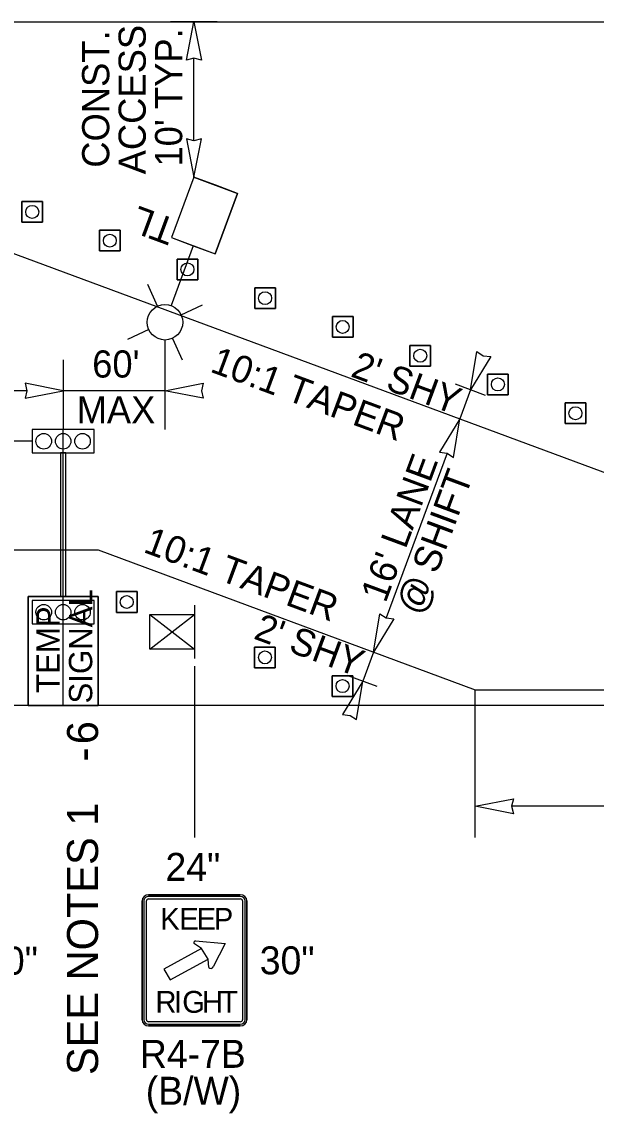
# Model space of a CAD drawing. Extents: x 99982 to 100176, y 99905 to 100011.
# Drawn here: x 100050.993 to 100052.474, y 99945.129 to 99947.939 of the extents above; entities that cross this region are included whole.
import ezdxf

# ---------------------------------------------------------------- set-up
doc = ezdxf.new("R2010")
doc.units = 0
for name, color, linetype in [('RD_ED_ShoulderPavedEdge', 7, 'Continuous'), ('RD_MK_LineEdgeWhite', 7, 'Continuous'), ('TR_SN_ConstructionSigns', 7, 'Continuous'), ('TR_WZ_PortableLightStandard', 7, 'Continuous'), ('TR_WZ_PortableSignMount5ftMinBlk-Wht', 7, 'Continuous'), ('TR_WZ_TempSignal', 7, 'Continuous'), ('TR_WZ_TrafficCone', 7, 'Continuous'), ('TR_WZ_WorkZoneDetails', 7, 'Continuous'), ('TR_WZ_WorkZoneTextCurrent', 7, 'Continuous')]:
    doc.layers.add(name, color=color, linetype=linetype)

msp = doc.modelspace()

# ---------------------------------------------------------------- linework, layer by layer
at = {"layer": 'RD_ED_ShoulderPavedEdge'}
for p, q in [((100040.1076, 99947.9393), (100055.45, 99947.9393)), ((100040.1076, 99946.1793), (100055.45, 99946.1793))]:
    msp.add_line(p, q, dxfattribs=at)
at = {"layer": 'RD_MK_LineEdgeWhite'}
for p, q in [((100050.4406, 99947.5393), (100052.9246, 99946.6193)), ((100040.1076, 99946.5793), (100051.1899, 99946.5793)), ((100051.1899, 99946.5793), (100052.1619, 99946.2193)), ((100052.1619, 99946.2193), (100055.45, 99946.2193))]:
    msp.add_line(p, q, dxfattribs=at)
at = {"layer": 'TR_SN_ConstructionSigns'}
for p, q in [((100051.3202, 99945.6913), (100051.5565, 99945.6913)), ((100051.5565, 99945.6913), (100051.3202, 99945.6913)), ((100051.5565, 99945.6869), (100051.3202, 99945.6869)), ((100051.3034, 99945.3696), (100051.3034, 99945.6755)), ((100051.3034, 99945.6755), (100051.3034, 99945.3696)), ((100051.308, 99945.6755), (100051.308, 99945.3696)), ((100051.3146, 99945.3696), (100051.3146, 99945.6755)), ((100051.3202, 99945.6808), (100051.5565, 99945.6808)), ((100051.5621, 99945.6755), (100051.5621, 99945.3696)), ((100051.5687, 99945.3696), (100051.5687, 99945.6755)), ((100051.5734, 99945.6755), (100051.5734, 99945.3696)), ((100051.5734, 99945.3696), (100051.5734, 99945.6755)), ((100051.4407, 99945.5725), (100051.5177, 99945.5656)), ((100051.4567, 99945.5529), (100051.359, 99945.5)), ((100051.4567, 99945.5529), (100051.4382, 99945.5647)), ((100051.4736, 99945.5255), (100051.4567, 99945.5529)), ((100051.4736, 99945.5255), (100051.4567, 99945.5529)), ((100051.4567, 99945.5529), (100051.4567, 99945.5529)), ((100051.5177, 99945.5656), (100051.4863, 99945.506)), ((100051.3758, 99945.4726), (100051.4736, 99945.5255)), ((100051.4752, 99945.5045), (100051.4736, 99945.5255)), ((100051.4736, 99945.5255), (100051.4736, 99945.5255)), ((100051.359, 99945.5), (100051.3758, 99945.4726)), ((100051.5565, 99945.3644), (100051.3202, 99945.3644)), ((100051.3202, 99945.3582), (100051.5565, 99945.3582)), ((100051.5565, 99945.3538), (100051.3202, 99945.3538)), ((100051.3202, 99945.3538), (100051.5565, 99945.3538))]:
    msp.add_line(p, q, dxfattribs=at)
for centre, major_axis, ratio, start_param, end_param in [((100051.3202, 99945.6755), (-0.0169, 0), 0.9375, 4.712389, 6.283185), ((100051.3202, 99945.6755), (-0.0169, 0), 0.9375, 4.712389, 6.283185), ((100051.3202, 99945.6755), (0.0122, 0), 0.9375, 1.570796, 3.141593), ((100051.5565, 99945.6755), (-0.0169, 0), 0.9375, 3.141593, 4.712389), ((100051.5565, 99945.6755), (-0.0169, 0), 0.9375, 3.141593, 4.712389), ((100051.5565, 99945.6755), (0.0122, 0), 0.9375, 0, 1.570796), ((100051.3202, 99945.6755), (0.00563, 0), 0.9375, 1.570796, 3.141593), ((100051.5565, 99945.6755), (0.00562, 0), 0.9375, 6.283185, 7.853982), ((100051.4415, 99945.568), (0.00485, -0.00001), 0.937492, 1.73335, 3.955171), ((100051.4804, 99945.5075), (0.00607, -0.00002), 0.9368, 3.700197, 6.020834), ((100051.3202, 99945.3696), (0.0169, 0), 0.9375, 3.141593, 4.712389), ((100051.3202, 99945.3696), (0.0169, 0), 0.9375, 3.141593, 4.712389), ((100051.3202, 99945.3696), (0.0122, 0), 0.9375, 3.141593, 4.712389), ((100051.3202, 99945.3696), (0.00563, 0), 0.9375, 3.141593, 4.712389), ((100051.5565, 99945.3696), (0.0169, 0), 0.9375, 4.712389, 6.283185), ((100051.5565, 99945.3696), (0.0122, 0), 0.9375, 4.712389, 6.283185), ((100051.5565, 99945.3696), (0.00562, 0), 0.9375, 4.712389, 6.283185), ((100051.5565, 99945.3696), (0.0169, 0), 0.9375, 4.712389, 6.283185)]:
    msp.add_ellipse(centre, major_axis=major_axis, ratio=ratio, start_param=start_param, end_param=end_param, dxfattribs=at)
at = {"layer": 'TR_WZ_PortableLightStandard'}
for p, q in [((100051.4367, 99947.5393), (100051.3791, 99947.3837)), ((100051.4367, 99947.5393), (100051.3791, 99947.3837)), ((100051.4367, 99947.5393), (100051.5492, 99947.4976)), ((100051.5492, 99947.4976), (100051.4916, 99947.342)), ((100051.4916, 99947.342), (100051.5492, 99947.4976)), ((100051.3791, 99947.3837), (100051.4916, 99947.342)), ((100051.4353, 99947.3628), (100051.3782, 99947.2087)), ((100051.3432, 99947.2073), (100051.3178, 99947.2626)), ((100051.4039, 99947.1848), (100051.4593, 99947.2103)), ((100051.3207, 99947.1467), (100051.2655, 99947.1212)), ((100051.3815, 99947.1242), (100051.4069, 99947.0688))]:
    msp.add_line(p, q, dxfattribs=at)
for points in [[(100051.5492, 99947.4976), (100051.493, 99947.5185), (100051.4367, 99947.5393)], [(100051.3791, 99947.3837), (100051.4353, 99947.3628), (100051.4916, 99947.342)]]:
    msp.add_lwpolyline(points, dxfattribs=at)
msp.add_circle((100051.3623, 99947.1657), 0.0457, dxfattribs=at)
msp.add_circle((100051.3623, 99947.1657), 0.0457, dxfattribs=at)
at = {"layer": 'TR_WZ_PortableSignMount5ftMinBlk-Wht'}
for p, q in [((100051.3233, 99946.3238), (100051.4384, 99946.4134)), ((100051.3233, 99946.4134), (100051.4384, 99946.3238)), ((100051.4384, 99946.4376), (100051.4384, 99946.2997)), ((100051.3807, 99946.3685), (100051.3807, 99946.3685)), ((100051.3808, 99946.3686), (100051.3808, 99946.3686))]:
    msp.add_line(p, q, dxfattribs=at)
msp.add_lwpolyline([(100051.3233, 99946.3238), (100051.3233, 99946.4134), (100051.4384, 99946.4134), (100051.4384, 99946.3238)], close=True, dxfattribs=at)
at = {"layer": 'TR_WZ_TempSignal'}
for p, q in [((100051.02, 99946.8893), (100051.02, 99946.8293)), ((100051.1798, 99946.8893), (100051.02, 99946.8893)), ((100051.0999, 99946.1789), (100051.0999, 99946.8893)), ((100051.1798, 99946.8293), (100051.1798, 99946.8893)), ((100051.02, 99946.8293), (100051.1798, 99946.8293)), ((100051.0932, 99946.8293), (100051.0932, 99946.4591)), ((100051.1065, 99946.8293), (100051.0932, 99946.8293)), ((100051.1065, 99946.4591), (100051.1065, 99946.8293)), ((100051.0098, 99946.1789), (100051.0098, 99946.4591)), ((100051.0098, 99946.4591), (100051.1899, 99946.4591)), ((100051.0932, 99946.4591), (100051.0098, 99946.4591)), ((100051.0098, 99946.4591), (100051.0098, 99946.1789)), ((100051.02, 99946.4491), (100051.02, 99946.3891)), ((100051.1798, 99946.4491), (100051.02, 99946.4491)), ((100051.0932, 99946.4591), (100051.1065, 99946.4591)), ((100051.1065, 99946.4591), (100051.0932, 99946.4591)), ((100051.1899, 99946.4591), (100051.1065, 99946.4591)), ((100051.1798, 99946.3891), (100051.1798, 99946.4491)), ((100051.1899, 99946.4591), (100051.1899, 99946.1789)), ((100051.1899, 99946.1789), (100051.1899, 99946.4591)), ((100051.02, 99946.3891), (100051.1798, 99946.3891)), ((100051.1899, 99946.1789), (100051.0098, 99946.1789)), ((100051.0098, 99946.1789), (100051.1899, 99946.1789))]:
    msp.add_line(p, q, dxfattribs=at)
for points in [[(100051.1798, 99946.8293), (100051.1798, 99946.8893), (100051.02, 99946.8893), (100051.02, 99946.8293), (100051.1798, 99946.8293)], [(100051.1798, 99946.3891), (100051.1798, 99946.4491), (100051.02, 99946.4491), (100051.02, 99946.3891), (100051.1798, 99946.3891)]]:
    msp.add_lwpolyline(points, dxfattribs=at)
for centre in [(100051.0499, 99946.8593), (100051.0499, 99946.8593), (100051.0999, 99946.8593), (100051.0999, 99946.8593), (100051.1498, 99946.8593), (100051.1498, 99946.8593), (100051.0499, 99946.4191), (100051.0499, 99946.4191), (100051.0999, 99946.4191), (100051.0999, 99946.4191), (100051.1498, 99946.4191), (100051.1498, 99946.4191)]:
    msp.add_circle(centre, 0.02, dxfattribs=at)
at = {"layer": 'TR_WZ_TrafficCone'}
for points in [[(100051.0469, 99947.4766), (100050.9936, 99947.4766), (100050.9936, 99947.4232), (100051.0469, 99947.4232), (100051.0469, 99947.4766)], [(100051.0469, 99947.4232), (100050.9936, 99947.4232), (100050.9936, 99947.4766), (100051.0469, 99947.4766), (100051.0469, 99947.4232)], [(100051.2469, 99947.4025), (100051.1936, 99947.4025), (100051.1936, 99947.3492), (100051.2469, 99947.3492), (100051.2469, 99947.4025)], [(100051.2469, 99947.3492), (100051.1936, 99947.3492), (100051.1936, 99947.4025), (100051.2469, 99947.4025), (100051.2469, 99947.3492)], [(100051.4469, 99947.3284), (100051.3936, 99947.3284), (100051.3936, 99947.2751), (100051.4469, 99947.2751), (100051.4469, 99947.3284)], [(100051.4469, 99947.2751), (100051.3936, 99947.2751), (100051.3936, 99947.3284), (100051.4469, 99947.3284), (100051.4469, 99947.2751)], [(100051.6469, 99947.2544), (100051.5936, 99947.2544), (100051.5936, 99947.201), (100051.6469, 99947.201), (100051.6469, 99947.2544)], [(100051.6469, 99947.201), (100051.5936, 99947.201), (100051.5936, 99947.2544), (100051.6469, 99947.2544), (100051.6469, 99947.201)], [(100051.8469, 99947.1803), (100051.7936, 99947.1803), (100051.7936, 99947.1269), (100051.8469, 99947.1269), (100051.8469, 99947.1803)], [(100051.8469, 99947.1269), (100051.7936, 99947.1269), (100051.7936, 99947.1803), (100051.8469, 99947.1803), (100051.8469, 99947.1269)], [(100052.0469, 99947.1062), (100051.9936, 99947.1062), (100051.9936, 99947.0529), (100052.0469, 99947.0529), (100052.0469, 99947.1062)], [(100052.0469, 99947.0529), (100051.9936, 99947.0529), (100051.9936, 99947.1062), (100052.0469, 99947.1062), (100052.0469, 99947.0529)], [(100052.2469, 99947.0321), (100052.1936, 99947.0321), (100052.1936, 99946.9788), (100052.2469, 99946.9788), (100052.2469, 99947.0321)], [(100052.2469, 99946.9788), (100052.1936, 99946.9788), (100052.1936, 99947.0321), (100052.2469, 99947.0321), (100052.2469, 99946.9788)], [(100052.4469, 99946.9581), (100052.3936, 99946.9581), (100052.3936, 99946.9047), (100052.4469, 99946.9047), (100052.4469, 99946.9581)], [(100052.4469, 99946.9047), (100052.3936, 99946.9047), (100052.3936, 99946.9581), (100052.4469, 99946.9581), (100052.4469, 99946.9047)], [(100051.237, 99946.472), (100051.2903, 99946.472), (100051.2903, 99946.4187), (100051.237, 99946.4187), (100051.237, 99946.472)], [(100051.237, 99946.4187), (100051.2903, 99946.4187), (100051.2903, 99946.472), (100051.237, 99946.472), (100051.237, 99946.4187)], [(100051.5933, 99946.3294), (100051.6466, 99946.3294), (100051.6466, 99946.2761), (100051.5933, 99946.2761), (100051.5933, 99946.3294)], [(100051.5933, 99946.2761), (100051.6466, 99946.2761), (100051.6466, 99946.3294), (100051.5933, 99946.3294), (100051.5933, 99946.2761)], [(100051.7933, 99946.2553), (100051.8466, 99946.2553), (100051.8466, 99946.202), (100051.7933, 99946.202), (100051.7933, 99946.2553)], [(100051.7933, 99946.202), (100051.8466, 99946.202), (100051.8466, 99946.2553), (100051.7933, 99946.2553), (100051.7933, 99946.202)]]:
    msp.add_lwpolyline(points, dxfattribs=at)
for centre in [(100051.0202, 99947.4499), (100051.2202, 99947.3758), (100051.4202, 99947.3018), (100051.6202, 99947.2277), (100051.8202, 99947.1536), (100052.0202, 99947.0795), (100052.2202, 99947.0055), (100052.4202, 99946.9314), (100051.2637, 99946.4453), (100051.62, 99946.3027), (100051.82, 99946.2287)]:
    msp.add_circle(centre, 0.0167, dxfattribs=at)
at = {"layer": 'TR_WZ_WorkZoneDetails'}
for p, q in [((100051.4967, 99947.9393), (100051.3767, 99947.9393)), ((100051.4367, 99947.633), (100051.4367, 99947.8456)), ((100051.3623, 99947.12), (100051.3623, 99946.8893)), ((100051.0999, 99947.0693), (100051.0999, 99946.8893)), ((100052.1883, 99946.9773), (100052.1111, 99947.0059)), ((100051.0061, 99946.9893), (100049.9513, 99946.9893)), ((100051.3623, 99946.9893), (100051.0999, 99946.9893)), ((100052.1497, 99946.9916), (100052.1219, 99946.9166)), ((100051.02, 99946.8593), (100050.86, 99946.8593)), ((100052.0894, 99946.8287), (100051.9322, 99946.4043)), ((100051.8996, 99946.3164), (100051.8718, 99946.2414)), ((100051.4384, 99946.2797), (100051.4384, 99945.8393)), ((100051.9094, 99946.2275), (100051.8322, 99946.2561)), ((100052.1619, 99945.8393), (100052.1619, 99946.2193)), ((100052.9532, 99945.9193), (100052.2556, 99945.9193))]:
    msp.add_line(p, q, dxfattribs=at)
for points in [[(100051.4367, 99947.9393), (100051.456, 99947.841), (100051.4367, 99947.8456), (100051.4174, 99947.841)], [(100051.4367, 99947.5393), (100051.456, 99947.6376), (100051.4367, 99947.633), (100051.4174, 99947.6376)], [(100052.1497, 99946.9916), (100052.1658, 99947.0905), (100052.1822, 99947.0795), (100052.2019, 99947.0771)], [(100051.0999, 99946.9893), (100051.0016, 99947.0085), (100051.0061, 99946.9893), (100051.0016, 99946.97)], [(100051.3623, 99946.9893), (100051.4606, 99947.0085), (100051.4561, 99946.9893), (100051.4606, 99946.97)], [(100052.1219, 99946.9166), (100052.0697, 99946.8311), (100052.0894, 99946.8287), (100052.1058, 99946.8177)], [(100051.8996, 99946.3164), (100051.9157, 99946.4153), (100051.9322, 99946.4043), (100051.9518, 99946.4019)], [(100051.8718, 99946.2414), (100051.8196, 99946.156), (100051.8393, 99946.1535), (100051.8558, 99946.1426)], [(100052.1619, 99945.9193), (100052.2602, 99945.9386), (100052.2556, 99945.9193), (100052.2602, 99945.9)]]:
    msp.add_lwpolyline(points, close=True, dxfattribs=at)

# ---------------------------------------------------------------- texts
at = {"layer": 'TR_SN_ConstructionSigns'}
for s, p in [('24"', (100051.3636, 99945.7273)), ('30"', (100050.8937, 99945.4858)), ('30"', (100051.6066, 99945.4866)), ('R4-7B', (100051.2977, 99945.2458)), ('(B/W)', (100051.3128, 99945.1507))]:
    msp.add_text(s, height=0.072, rotation=360, dxfattribs=at).set_placement(p)
for s, p in [('K', (100051.3503, 99945.6013)), ('E', (100051.3993, 99945.6013)), ('E', (100051.4437, 99945.6013)), ('P', (100051.4881, 99945.6013)), ('R', (100051.3377, 99945.3876)), ('I', (100051.3855, 99945.3876)), ('G', (100051.4069, 99945.3876)), ('H', (100051.4575, 99945.3876)), ('T', (100051.5042, 99945.3876))]:
    msp.add_text(s, height=0.0562, dxfattribs=at).set_placement(p)
at = {"layer": 'TR_WZ_PortableLightStandard'}
msp.add_text('TL', height=0.07, rotation=159.6769, dxfattribs=at).set_placement((100051.3958, 99947.4287))
at = {"layer": 'TR_WZ_TempSignal'}
for s, p in [('SIGNAL', (100051.1748, 99946.184)), ('TEMP', (100051.0908, 99946.2111))]:
    msp.add_text(s, height=0.06, rotation=90, dxfattribs=at).set_placement(p)
at = {"layer": 'TR_WZ_WorkZoneTextCurrent'}
for s, height, rotation, p in [('CONST.', 0.07, 90, (100051.2187, 99947.5637)), ('ACCESS', 0.07, 90, (100051.3127, 99947.5465)), ("10' TYP.", 0.07, 90, (100051.4067, 99947.5666)), ("60'", 0.07, 360, (100051.1748, 99947.0233)), ('10:1 TAPER', 0.07, 339.6769, (100051.4758, 99947.0392)), ("2' SHY", 0.07, 339.6769, (100051.838, 99947.0271)), ('MAX', 0.07, 360, (100051.1346, 99946.9053)), ("16' LANE", 0.07, 69.6769, (100051.9308, 99946.4408)), ('SHIFT', 0.07, 69.6769, (100052.063, 99946.5156)), ('10:1 TAPER', 0.07, 339.6769, (100051.3038, 99946.5747)), ('@', 0.07, 69.6769, (100052.023, 99946.4077)), ("2' SHY", 0.07, 339.6769, (100051.5879, 99946.3519)), ('6', 0.08, 90, (100051.1899, 99946.079)), ('-', 0.08, 90, (100051.1899, 99946.0349)), ('SEE NOTES 1', 0.08, 90, (100051.1899, 99945.2272))]:
    msp.add_text(s, height=height, rotation=rotation, dxfattribs=at).set_placement(p)

doc.saveas('drawing.dxf')
